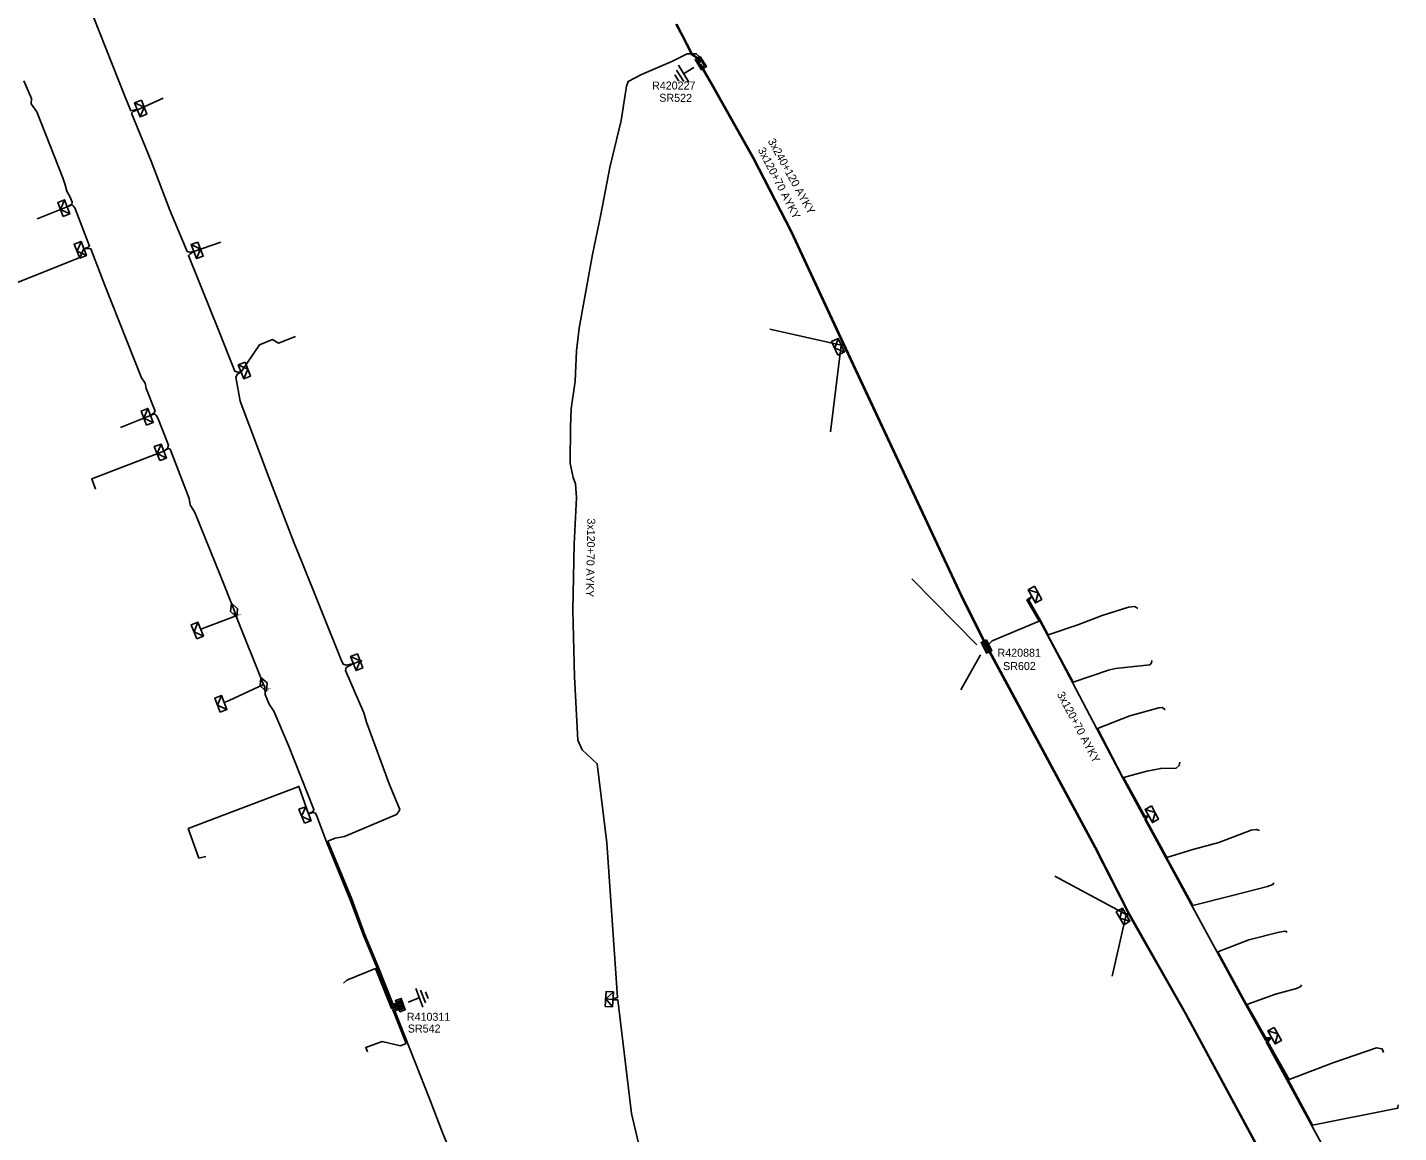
# Model space of a CAD drawing. Extents: x -540028 to -538776, y -1157064 to -1155670.
# Drawn here: x -539686.8 to -539515.4, y -1156494.9 to -1156356.7 of the extents above; entities that cross this region are included whole.
import ezdxf

# ---------------------------------------------------------------- set-up
doc = ezdxf.new("R2010")
doc.units = 0
for name, color, linetype in [('Vrstva 15', 7, 'Continuous'), ('Vrstva 19', 7, 'Continuous'), ('Vrstva 2', 7, 'Continuous'), ('Vrstva 28', 7, 'Continuous'), ('Vrstva 29', 7, 'Continuous'), ('Vrstva 30', 7, 'Continuous'), ('Vrstva 31', 7, 'Continuous'), ('Vrstva 5', 7, 'Continuous'), ('Vrstva 52', 7, 'Continuous'), ('Vrstva 59', 7, 'Continuous'), ('Vrstva 6', 7, 'Continuous')]:
    doc.layers.add(name, color=color, linetype=linetype)

# ---------------------------------------------------------------- blocks, each defined once
blk = doc.blocks.new('17.1')
at = {"layer": 'Vrstva 2'}
blk.add_lwpolyline([(-1.875, 0), (0, 0.9375), (1.875, 0), (0, -0.9375)], close=True, dxfattribs=at)
blk.add_text('T', height=0.75, dxfattribs=at).set_placement((-1.875, -1.35))
blk = doc.blocks.new('132')
at = {"layer": 'Vrstva 2'}
for points in [[(-1.5, 1.5), (1.5, 1.5), (1.5, 0), (-1.5, 0)], [(-1.1, 1.2), (1.1, 1.2), (1.1, 0.3), (-1.1, 0.3)]]:
    blk.add_lwpolyline(points, close=True, dxfattribs=at)
blk = doc.blocks.new('23')
at = {"layer": 'Vrstva 2'}
blk.add_lwpolyline([(1.875, -1.8), (-1.875, -1.8), (-1.875, 0), (1.875, 0)], close=True, dxfattribs=at)
blk.add_lwpolyline([(1.875, 0), (0, -1.8), (-1.875, 0)], dxfattribs=at)
blk = doc.blocks.new('11')
at = {"layer": 'Vrstva 2'}
for p, q in [((0, -4.3), (0, -1.3)), ((-2.5, -4.3), (2.5, -4.3)), ((-1.7, -5.3), (1.7, -5.3)), ((-0.9, -6.3), (0.9, -6.3))]:
    blk.add_line(p, q, dxfattribs=at)

msp = doc.modelspace()

# ---------------------------------------------------------------- linework, layer by layer
at = {"layer": 'Vrstva 5'}
for points in [[(-539678.54, -1156355.32), (-539674.6, -1156365.29), (-539673.83, -1156367.13), (-539673.16, -1156366.95), (-539673.02, -1156367.02), (-539673.54, -1156367.23), (-539673.73, -1156367.41), (-539671.3, -1156373.45), (-539668.94, -1156379.55), (-539666.8, -1156384.74), (-539666.53, -1156384.79), (-539665.96, -1156384.74), (-539666.46, -1156385.04), (-539666.64, -1156385.21), (-539662.73, -1156394.87), (-539661.57, -1156397.82), (-539660.82, -1156399.69), (-539660.51, -1156399.81), (-539660.06, -1156399.77), (-539660.52, -1156400.05), (-539660.69, -1156400.43), (-539660.17, -1156403.45), (-539656.56, -1156413.07), (-539653.42, -1156421.18), (-539652.54, -1156423.33), (-539647.53, -1156435.78), (-539647.31, -1156436.34), (-539646.92, -1156436.44), (-539646.02, -1156436.24), (-539646.9, -1156436.73), (-539647.01, -1156437.12), (-539644.7, -1156442.4), (-539644.38, -1156443.58), (-539641.54, -1156451.3), (-539640.21, -1156454.5), (-539640.39, -1156454.78), (-539640.62, -1156455.12), (-539647.13, -1156457.88), (-539648.3, -1156458.08), (-539649.2, -1156458.46), (-539646.22, -1156465.71), (-539644.63, -1156470.05), (-539642.86, -1156474.24), (-539641.03, -1156478.87), (-539639.93, -1156478.45)], [(-539603.01, -1156361.16), (-539602.76, -1156361.07), (-539602.92, -1156360.65), (-539603.69, -1156360.14), (-539604.9, -1156357.76), (-539605.69, -1156356.31)], [(-539605.59, -1156356.29), (-539603.61, -1156360.08), (-539602.84, -1156360.59), (-539602.66, -1156361.03), (-539602.89, -1156361.35)], [(-539607.73, -1156507.35), (-539611.23, -1156492.5), (-539612.97, -1156478.27), (-539613.51, -1156478.28), (-539613.57, -1156478.23), (-539613.52, -1156478.16), (-539613, -1156478), (-539614.35, -1156458.64), (-539615.54, -1156448.78), (-539617.42, -1156447.03), (-539617.96, -1156445.82), (-539618.38, -1156437.89), (-539618.57, -1156429.55), (-539618.4, -1156421.3), (-539618.13, -1156415.47), (-539618.25, -1156413.79), (-539618.54, -1156412.98), (-539618.93, -1156411.22), (-539618.86, -1156406.63), (-539618.79, -1156404.38), (-539618.31, -1156400.93), (-539618.14, -1156397.15), (-539617.78, -1156394.33), (-539616.13, -1156385.12), (-539615.08, -1156380.11), (-539613.95, -1156374.22), (-539612.54, -1156368.35), (-539611.89, -1156364.05), (-539611.66, -1156363.45), (-539610, -1156362.6), (-539606.2, -1156360.95), (-539604.31, -1156360.02), (-539603.15, -1156360), (-539602.66, -1156360.47), (-539602.61, -1156360.84), (-539602.93, -1156361.29)], [(-539602.82, -1156361.46), (-539602.58, -1156361.33), (-539601.15, -1156363.8), (-539595.97, -1156373.04), (-539591.24, -1156382.19), (-539584.72, -1156396.21), (-539569.94, -1156427.78), (-539566.81, -1156434.09), (-539553.26, -1156459.19), (-539549.07, -1156467.4), (-539541.94, -1156479.99), (-539529.28, -1156503.41), (-539522.68, -1156515.3), (-539517.91, -1156524.32), (-539516.6, -1156527.01), (-539515.37, -1156529.13), (-539515.71, -1156529.28)], [(-539602.76, -1156361.56), (-539602.6, -1156361.57), (-539601.23, -1156363.85), (-539596.05, -1156373.08), (-539591.33, -1156382.23), (-539584.83, -1156396.22), (-539585.03, -1156396.44), (-539584.74, -1156396.4), (-539570.03, -1156427.82), (-539566.95, -1156434.03), (-539567.24, -1156434.2)], [(-539687.19, -1156363.4), (-539686.27, -1156365.6), (-539686.29, -1156366.28), (-539685.57, -1156367.26), (-539682.33, -1156375.51), (-539682.03, -1156376.4), (-539681.84, -1156377.19), (-539681.43, -1156377.93), (-539681.17, -1156378.56), (-539681.21, -1156378.81), (-539681.78, -1156379.13), (-539681.17, -1156378.89), (-539681.03, -1156379.02), (-539680.83, -1156379.27), (-539678.98, -1156384.04), (-539679.19, -1156384.23), (-539679.72, -1156384.34), (-539679.16, -1156384.36), (-539678.82, -1156384.39), (-539677.12, -1156388.86), (-539672.48, -1156400.5), (-539672.03, -1156401.2), (-539671.9, -1156401.87), (-539670.79, -1156404.7), (-539670.95, -1156404.94), (-539671.36, -1156405.22), (-539670.93, -1156405.04), (-539670.66, -1156405.2), (-539670.43, -1156405.64), (-539669.11, -1156408.95), (-539669.22, -1156409.25), (-539669.72, -1156409.67), (-539669.15, -1156409.37), (-539668.93, -1156409.44), (-539666.54, -1156415.59), (-539666.42, -1156416.41), (-539665.85, -1156417.37), (-539662.62, -1156425.28), (-539660.93, -1156429.57), (-539660.69, -1156430.25), (-539657.23, -1156438.85), (-539657.09, -1156439.16), (-539657.03, -1156440.11), (-539656.53, -1156441.31), (-539655.95, -1156442.18), (-539654.12, -1156446.5), (-539650.94, -1156454.48), (-539651.06, -1156454.74), (-539651.64, -1156455.02), (-539651.05, -1156454.85), (-539650.74, -1156454.96), (-539650.59, -1156455.34), (-539649.39, -1156458.53), (-539646.4, -1156465.79), (-539644.81, -1156470.13), (-539643.05, -1156474.32), (-539641.14, -1156479.13), (-539639.86, -1156478.64)], [(-539567.2, -1156434.27), (-539566.86, -1156434.1), (-539566.17, -1156433.4), (-539560.29, -1156430.95), (-539561.83, -1156428.29), (-539561.21, -1156427.84)], [(-539561.21, -1156427.84), (-539561.71, -1156428.3), (-539560.21, -1156430.9), (-539559.27, -1156432.69), (-539556.14, -1156438.6), (-539553.08, -1156444.39), (-539549.89, -1156450.5), (-539547.18, -1156455.49), (-539546.6, -1156455.3)], [(-539567.16, -1156434.35), (-539566.84, -1156434.23), (-539553.34, -1156459.23), (-539549.17, -1156467.41), (-539549.41, -1156467.64), (-539549.08, -1156467.61), (-539542.02, -1156480.03), (-539529.36, -1156503.45), (-539522.79, -1156515.3), (-539523, -1156515.51), (-539522.69, -1156515.47), (-539517.99, -1156524.36), (-539516.68, -1156527.05), (-539515.53, -1156529.13), (-539515.76, -1156529.19)], [(-539546.6, -1156455.3), (-539547.07, -1156455.68), (-539534.66, -1156478.53), (-539532.02, -1156483.32), (-539531.26, -1156482.99)], [(-539639.64, -1156479.2), (-539640.83, -1156479.65), (-539636.44, -1156490.74), (-539634.84, -1156495.01), (-539633.5, -1156498.18), (-539630.36, -1156506.13), (-539628.73, -1156510.19), (-539628.93, -1156510.53), (-539630.45, -1156511.13), (-539630.58, -1156510.31)], [(-539531.26, -1156482.99), (-539531.9, -1156483.53), (-539519.84, -1156505.77), (-539517.11, -1156511.16), (-539516.11, -1156510.83)]]:
    msp.add_lwpolyline(points, dxfattribs=at)
at = {"layer": 'Vrstva 52'}
for points in [[(-539673.02, -1156367.02), (-539669.78, -1156365.55)], [(-539681.78, -1156379.13), (-539685.55, -1156380.62)], [(-539665.96, -1156384.74), (-539662.6, -1156383.57)], [(-539679.72, -1156384.34), (-539680.19, -1156385.49), (-539690.76, -1156389.67), (-539692.53, -1156390.05), (-539691.46, -1156392.86)], [(-539660.06, -1156399.77), (-539657.77, -1156396.38), (-539656.14, -1156395.74), (-539655.39, -1156396.19), (-539653.26, -1156395.35)], [(-539671.36, -1156405.22), (-539675.13, -1156406.75)], [(-539669.72, -1156409.67), (-539678.72, -1156413.15), (-539678.23, -1156414.42)], [(-539568.1, -1156433.89), (-539576.21, -1156425.64)], [(-539561.21, -1156427.84), (-539561.65, -1156428.31), (-539560.18, -1156430.85), (-539559.21, -1156432.68), (-539556.06, -1156438.57), (-539551.61, -1156437.05), (-539550.75, -1156436.88), (-539546.45, -1156436.39), (-539546.25, -1156436.16), (-539546.22, -1156435.88)], [(-539561.21, -1156427.84), (-539561.6, -1156428.32), (-539560.13, -1156430.85), (-539559.17, -1156432.66), (-539555.46, -1156431.39), (-539552.4, -1156430.23), (-539549.13, -1156429.18), (-539548.35, -1156429.12), (-539547.96, -1156429.37)], [(-539660.93, -1156429.57), (-539660.8, -1156430.31), (-539665.1, -1156431.93)], [(-539567.63, -1156435.16), (-539570.1, -1156439.51)], [(-539646.02, -1156436.24), (-539644.93, -1156435.86)], [(-539657.23, -1156438.85), (-539661.54, -1156440.86), (-539662.17, -1156441.11)], [(-539546.6, -1156455.3), (-539547.14, -1156455.41), (-539549.86, -1156450.41), (-539553.01, -1156444.36), (-539548.95, -1156442.77), (-539545.34, -1156441.77), (-539544.89, -1156441.75), (-539544.54, -1156442.05)], [(-539546.6, -1156455.3), (-539547.1, -1156455.32), (-539549.75, -1156450.47), (-539546.84, -1156449.68), (-539545.09, -1156449.36), (-539543.18, -1156449.33), (-539542.8, -1156448.97), (-539542.73, -1156448.56)], [(-539651.64, -1156455.02), (-539652.85, -1156451.61), (-539666.65, -1156456.88), (-539665.33, -1156460.56), (-539664.45, -1156460.36)], [(-539546.6, -1156455.3), (-539547.01, -1156455.7), (-539544.39, -1156460.5), (-539541.09, -1156466.49), (-539536.3, -1156465.28), (-539531.74, -1156464.11), (-539531.1, -1156463.87), (-539530.95, -1156463.68)], [(-539546.6, -1156455.3), (-539546.95, -1156455.71), (-539544.34, -1156460.49), (-539541.09, -1156459.48), (-539537.83, -1156458.62), (-539533.78, -1156457.08), (-539533.15, -1156456.99), (-539532.74, -1156457.13)], [(-539531.26, -1156482.99), (-539531.99, -1156483.17), (-539534.64, -1156478.43), (-539537.98, -1156472.28), (-539534.1, -1156470.77), (-539530.3, -1156469.83), (-539529.55, -1156469.69), (-539529.29, -1156469.83)], [(-539639.79, -1156478.82), (-539641.26, -1156479.39), (-539643.23, -1156474.39), (-539646.84, -1156475.85), (-539647.25, -1156476.19)], [(-539531.26, -1156482.99), (-539531.97, -1156483.05), (-539534.32, -1156478.87), (-539530.77, -1156477.6), (-539528.11, -1156476.87), (-539527.6, -1156476.64), (-539527.5, -1156476.42)], [(-539639.71, -1156479.01), (-539641.09, -1156479.53), (-539639.42, -1156483.74), (-539640.13, -1156484.02), (-539642.41, -1156483.5), (-539644.46, -1156484.23), (-539644.23, -1156484.81)], [(-539531.26, -1156482.99), (-539531.79, -1156483.54), (-539529.17, -1156488.29), (-539526.12, -1156493.94), (-539515.48, -1156491.85), (-539515.43, -1156491.42)], [(-539531.26, -1156482.99), (-539531.69, -1156483.55), (-539529.04, -1156488.27), (-539523.46, -1156486.11), (-539518.14, -1156484.31), (-539517.42, -1156484.41), (-539517.24, -1156484.87)]]:
    msp.add_lwpolyline(points, dxfattribs=at)
at = {"layer": 'Vrstva 59'}
for points in [[(-539585.03, -1156396.44), (-539593.97, -1156394.45)], [(-539585.03, -1156396.44), (-539586.36, -1156407.29)], [(-539549.41, -1156467.64), (-539558.32, -1156462.83)], [(-539549.41, -1156467.64), (-539551.18, -1156475.35)], [(-539613.57, -1156478.23), (-539614.57, -1156478.16)]]:
    msp.add_lwpolyline(points, dxfattribs=at)

# ---------------------------------------------------------------- block references
at = {"layer": 'Vrstva 15'}
for p, xscale, yscale, rotation in [((-539602.91, -1156361.36), 0.5000000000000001, 0.4999999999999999, -57.99999998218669), ((-539639.79, -1156478.82), 0.5, 0.5, 110.8846111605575)]:
    msp.add_blockref('11', p, dxfattribs=dict(at, xscale=xscale, yscale=yscale, rotation=rotation))
at = {"layer": 'Vrstva 19', "xscale": 0.5, "yscale": 0.5}
for p, rotation in [((-539660.93, -1156429.57), 111.2225722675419), ((-539657.23, -1156438.85), 112.25514161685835)]:
    msp.add_blockref('17.1', p, dxfattribs=dict(at, rotation=rotation))
at = {"layer": 'Vrstva 28', "xscale": 0.5}
for p, yscale, rotation in [((-539602.91, -1156361.36), 0.5, -58.000000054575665), ((-539567.22, -1156434.29), 0.5, -63.9999999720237), ((-539639.79, -1156478.82), 0.5000000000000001, 110.88461111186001)]:
    msp.add_blockref('132', p, dxfattribs=dict(at, yscale=yscale, rotation=rotation))
at = {"layer": 'Vrstva 31'}
for p, xscale, yscale, rotation in [((-539673.02, -1156367.02), 0.5, 0.49999999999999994, 111.03751115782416), ((-539681.78, -1156379.13), 0.5, 0.5, -68.96248895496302), ((-539679.72, -1156384.34), 0.49999999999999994, 0.5000000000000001, -68.96248889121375), ((-539665.96, -1156384.74), 0.5, 0.5, 111.03751109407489), ((-539585.03, -1156396.44), 0.49999999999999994, 0.5000000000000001, -65.00000002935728), ((-539660.06, -1156399.77), 0.5, 0.49999999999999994, 111.03751115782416), ((-539671.36, -1156405.22), 0.49999999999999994, 0.5000000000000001, -68.96248884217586), ((-539669.72, -1156409.67), 0.49999999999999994, 0.5000000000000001, -68.96248884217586), ((-539561.21, -1156427.84), 0.5000000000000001, 0.5, 119.00000004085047), ((-539665.1, -1156431.93), 0.5, 0.5, -68.37059724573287), ((-539646.02, -1156436.24), 0.5, 0.49999999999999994, 111.03751115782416), ((-539662.17, -1156441.11), 0.49999999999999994, 0.5000000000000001, -68.85390559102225), ((-539651.64, -1156455.02), 0.49999999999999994, 0.5000000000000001, -68.96248890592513), ((-539546.6, -1156455.3), 0.5, 0.5, 118.9999999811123), ((-539549.41, -1156467.64), 0.5, 0.5, -59.99999997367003), ((-539613.57, -1156478.23), 0.5, 0.5, -94.00000003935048), ((-539531.26, -1156482.99), 0.5, 0.5, 118.9999999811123)]:
    msp.add_blockref('23', p, dxfattribs=dict(at, xscale=xscale, yscale=yscale, rotation=rotation))

# ---------------------------------------------------------------- texts
at = {"layer": 'Vrstva 29'}
for s, p in [('R420227', (-539608.68, -1156364.47)), ('R420881', (-539565.5, -1156435.39))]:
    msp.add_text(s, height=1, dxfattribs=at).set_placement(p)
msp.add_text('R410311', height=1, rotation=0.03, dxfattribs=at).set_placement((-539639.33, -1156480.91))
at = {"layer": 'Vrstva 30'}
for s, rotation, p in [('SR522', 359.706, (-539607.78, -1156366)), ('SR602', 0.42, (-539564.8, -1156437.07)), ('SR542', 0.021, (-539639.21, -1156482.38))]:
    msp.add_text(s, height=1, rotation=rotation, dxfattribs=at).set_placement(p)
at = {"layer": 'Vrstva 6'}
for s, rotation, p in [('3x120+70 AYKY', 297.287, (-539595.49, -1156372.02)), ('3x240+120 AYKY', 299, (-539594.25, -1156370.92)), ('3x120+70 AYKY', 268.82, (-539616.76, -1156418.09)), ('3x120+70 AYKY', 298, (-539558.11, -1156440.07))]:
    msp.add_text(s, height=1, rotation=rotation, dxfattribs=at).set_placement(p)

doc.saveas('drawing.dxf')
